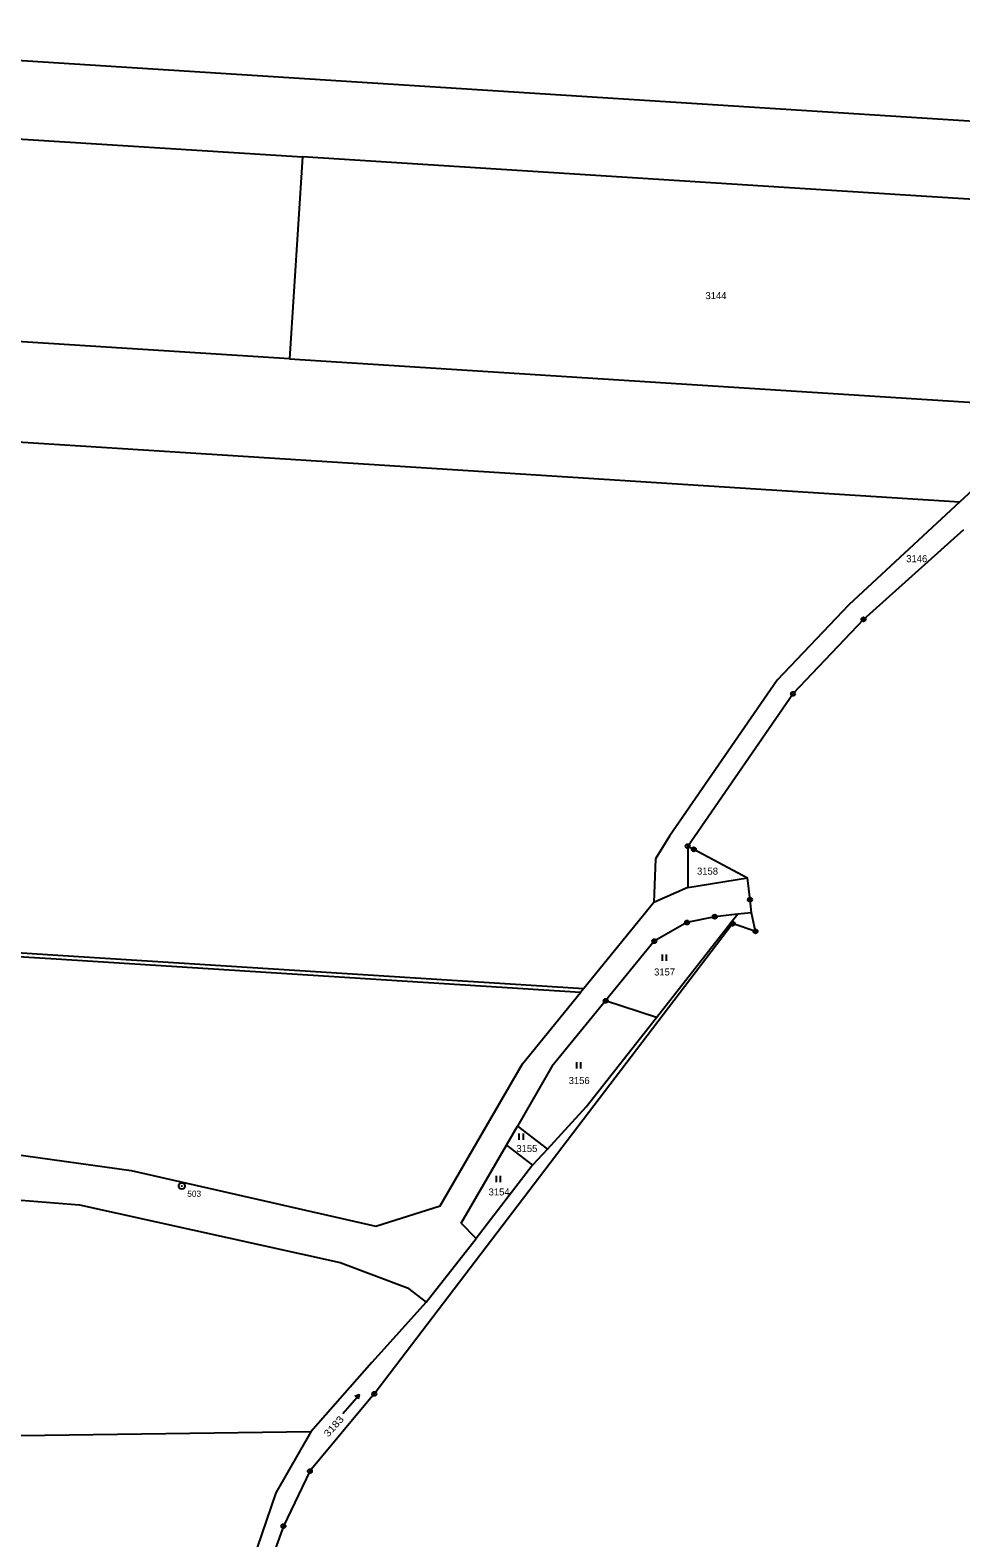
# Model space of a CAD drawing. Extents: x -618848 to -615803, y -1044450 to -1042254.
# Drawn here: x -616256.9 to -616032.4, y -1043038.9 to -1042674.9 of the extents above; entities that cross this region are included whole.
import ezdxf

# ---------------------------------------------------------------- set-up
doc = ezdxf.new("R2010")
doc.units = 0
doc.header["$LTSCALE"] = 0.68
for name, color, linetype, lineweight in [('1', 7, 'Continuous', 25), ('3', 7, 'Continuous', 25), ('8', 7, 'Continuous', 25)]:
    doc.layers.add(name, color=color, linetype=linetype, lineweight=lineweight)
doc.layers.add('2', color=7, linetype='Continuous')

msp = doc.modelspace()

# ---------------------------------------------------------------- linework, layer by layer
at = {"layer": '1'}
for p, q in [((-616231.12, -1042684.09), (-616375.02, -1042674.92)), ((-616087.21, -1042693.25), (-616231.12, -1042684.09)), ((-616375.23, -1042693.79), (-616191.24, -1042705.51)), ((-615943.31, -1042702.42), (-616087.21, -1042693.25)), ((-616191.24, -1042705.51), (-616194.35, -1042754.28)), ((-616075.02, -1042712.91), (-616191.24, -1042705.51)), ((-615958.79, -1042720.31), (-616075.02, -1042712.91)), ((-616194.35, -1042754.28), (-616375.73, -1042742.75)), ((-616194.35, -1042754.28), (-616008.21, -1042766.14)), ((-616375.91, -1042766.94), (-616204.28, -1042777.88)), ((-616032.64, -1042788.81), (-616008.21, -1042766.14)), ((-616204.28, -1042777.88), (-616032.64, -1042788.81)), ((-616032.64, -1042788.81), (-616059.39, -1042813.61)), ((-616055.87, -1042817.16), (-616031.62, -1042795.47)), ((-616059.39, -1042813.61), (-616076.66, -1042831.84)), ((-616055.87, -1042817.16), (-616072.89, -1042835.13)), ((-616076.66, -1042831.84), (-616102.67, -1042869.52)), ((-616098.28, -1042871.91), (-616072.89, -1042835.13)), ((-616102.67, -1042869.52), (-616106.06, -1042874.94)), ((-616098.28, -1042871.91), (-616098.23, -1042881.89)), ((-616106.06, -1042874.94), (-616106.43, -1042885.54)), ((-616098.23, -1042881.89), (-616083.88, -1042879.57)), ((-616083.25, -1042884.84), (-616083.88, -1042879.57)), ((-616098.23, -1042881.89), (-616106.43, -1042885.54)), ((-616106.43, -1042885.54), (-616123.35, -1042906.28)), ((-616082.87, -1042888), (-616083.25, -1042884.84)), ((-616377.11, -1042890.12), (-616250.23, -1042898.2)), ((-616173.91, -1043004.12), (-616087.44, -1042890.61)), ((-616098.47, -1042890.35), (-616106.34, -1042894.84)), ((-616105.84, -1042913.28), (-616086.26, -1042888.36)), ((-616091.75, -1042888.94), (-616098.47, -1042890.35)), ((-616086.26, -1042888.36), (-616091.75, -1042888.94)), ((-616081.92, -1042892.47), (-616087.44, -1042890.61)), ((-616082.87, -1042888), (-616086.26, -1042888.36)), ((-616081.92, -1042892.47), (-616082.87, -1042888)), ((-616250.63, -1042899.2), (-616377.12, -1042891.14)), ((-616106.34, -1042894.84), (-616118.09, -1042909.24)), ((-616124.14, -1042907.25), (-616250.63, -1042899.2)), ((-616250.23, -1042898.2), (-616123.35, -1042906.28)), ((-616138.15, -1042924.42), (-616124.14, -1042907.25)), ((-616123.35, -1042906.28), (-616124.14, -1042907.25)), ((-616118.09, -1042909.24), (-616131.04, -1042925.12)), ((-616105.84, -1042913.28), (-616118.09, -1042909.24)), ((-616122.78, -1042934.83), (-616105.84, -1042913.28)), ((-616158.04, -1042958.72), (-616138.15, -1042924.42)), ((-616131.04, -1042925.12), (-616139.35, -1042939.46)), ((-616132.11, -1042945.02), (-616122.78, -1042934.83)), ((-616142.03, -1042944.08), (-616139.35, -1042939.46)), ((-616139.35, -1042939.46), (-616132.11, -1042945.02)), ((-616152.94, -1042962.91), (-616142.03, -1042944.08)), ((-616142.03, -1042944.08), (-616135.7, -1042948.94)), ((-616132.11, -1042945.02), (-616135.7, -1042948.94)), ((-616261.43, -1042946.19), (-616232.54, -1042950.22)), ((-616135.7, -1042948.94), (-616149.3, -1042966.64)), ((-616232.54, -1042950.22), (-616173.56, -1042963.62)), ((-616275.67, -1042956.05), (-616245.06, -1042958.45)), ((-616245.06, -1042958.45), (-616182.17, -1042972.39)), ((-616173.56, -1042963.62), (-616158.04, -1042958.72)), ((-616149.3, -1042966.64), (-616152.94, -1042962.91)), ((-616161.38, -1042981.97), (-616149.3, -1042966.64)), ((-616182.17, -1042972.39), (-616165.86, -1042978.54)), ((-616165.86, -1042978.54), (-616161.38, -1042981.97)), ((-616161.38, -1042981.97), (-616174.48, -1042996.55)), ((-616174.48, -1042996.55), (-616189.22, -1043013.27)), ((-616173.91, -1043004.12), (-616189.44, -1043022.78)), ((-616189.22, -1043013.27), (-616337.34, -1043015.38)), ((-616189.22, -1043013.27), (-616197.66, -1043027.98)), ((-616189.44, -1043022.78), (-616195.83, -1043036.06)), ((-616197.66, -1043027.98), (-616202.14, -1043041.2)), ((-616195.83, -1043036.06), (-616203.75, -1043057.83))]:
    msp.add_line(p, q, dxfattribs=at)
msp.add_lwpolyline([(-616098.28, -1042871.91), (-616096.81, -1042872.66), (-616083.88, -1042879.57)], dxfattribs=at)
at = {"layer": '3'}
for p, q in [((-616104.401, -1042899.56), (-616104.401, -1042898.06)), ((-616103.4, -1042899.56), (-616103.4, -1042898.06)), ((-616125.041, -1042925.55), (-616125.041, -1042924.05)), ((-616124.04, -1042925.55), (-616124.04, -1042924.05)), ((-616138.921, -1042942.81), (-616138.921, -1042941.31)), ((-616137.92, -1042942.81), (-616137.92, -1042941.31)), ((-616144.431, -1042952.98), (-616144.431, -1042951.48)), ((-616143.43, -1042952.98), (-616143.43, -1042951.48)), ((-616177.544, -1043004.319), (-616177.807, -1043005.385))]:
    msp.add_line(p, q, dxfattribs=at)
msp.add_lwpolyline([(-616181.48, -1043008.847), (-616177.544, -1043004.319), (-616178.564, -1043004.727)], dxfattribs=at)
at = {"layer": '8'}
for centre, radius in [((-616055.87, -1042817.1599), 0.5), ((-616055.87, -1042817.1599), 0.0303), ((-616072.89, -1042835.1299), 0.5), ((-616072.89, -1042835.1299), 0.0303), ((-616098.28, -1042871.9101), 0.5), ((-616098.28, -1042871.9101), 0.0303), ((-616096.81, -1042872.6601), 0.5), ((-616096.81, -1042872.6601), 0.0303), ((-616083.25, -1042884.8401), 0.5), ((-616083.25, -1042884.8401), 0.0303), ((-616098.47, -1042890.3499), 0.5), ((-616098.47, -1042890.3499), 0.0303), ((-616091.75, -1042888.9399), 0.5), ((-616091.75, -1042888.9399), 0.0303), ((-616087.44, -1042890.6101), 0.5), ((-616087.44, -1042890.6101), 0.0303), ((-616106.34, -1042894.8399), 0.5), ((-616081.92, -1042892.4701), 0.5), ((-616081.92, -1042892.4701), 0.0303), ((-616106.34, -1042894.8399), 0.0303), ((-616118.09, -1042909.2399), 0.5), ((-616118.09, -1042909.2399), 0.0303), ((-616220.34, -1042953.9298), 0.75), ((-616220.34, -1042953.9298), 0.03), ((-616173.91, -1043004.1201), 0.5), ((-616173.91, -1043004.1201), 0.0303), ((-616189.44, -1043022.7801), 0.5), ((-616189.44, -1043022.7801), 0.0303), ((-616195.83, -1043036.0599), 0.5), ((-616195.83, -1043036.0599), 0.0303)]:
    msp.add_circle(centre, radius, dxfattribs=at)

# ---------------------------------------------------------------- texts
at = {"layer": '2'}
for s, p in [('3144', (-616093.99, -1042739.855)), ('3146', (-616045.55, -1042803.355)), ('3158', (-616096.03, -1042878.785)), ('3157', (-616106.39, -1042903.125)), ('3156', (-616127, -1042929.335)), ('3155', (-616139.62, -1042945.745)), ('3154', (-616146.32, -1042956.225))]:
    msp.add_text(s, height=1.7, dxfattribs=at).set_placement(p)
at = {"layer": '2', "width": 1.15}
msp.add_text('3183', height=1.7, rotation=48, dxfattribs=at).set_placement((-616185.004, -1043014.684))
at = {"layer": '8'}
msp.add_text('503', height=1.5, dxfattribs=at).set_placement((-616219.03, -1042956.555))

doc.saveas('drawing.dxf')
